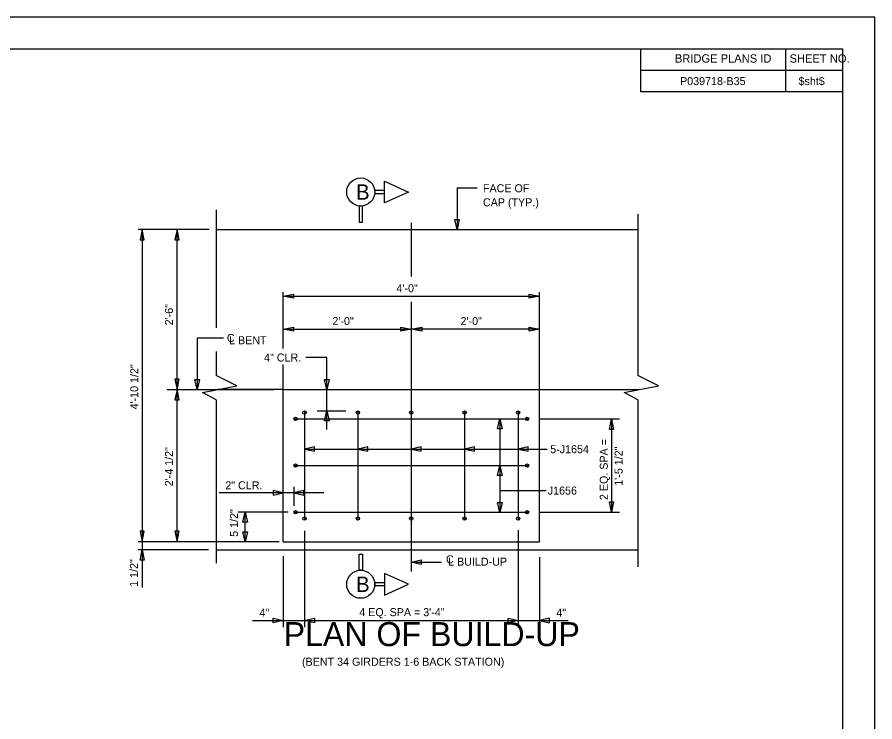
# Model space of a CAD drawing. Extents: x -133.1 to -97, y -110.1 to -88.1.
# Drawn here: x -110.53 to -97.14, y -99.1 to -88.1 of the extents above; entities that cross this region are included whole.
import ezdxf

# ---------------------------------------------------------------- set-up
doc = ezdxf.new("R2010")
doc.units = 0
for name, color, linetype in [('BR_AUTO DIMENSION', 7, 'Continuous'), ('BR_BORDER LINES', 7, 'Continuous'), ('BR_CENTER LINES', 7, 'Continuous'), ('BR_CONCRETE', 7, 'Continuous'), ('BR_REBAR', 7, 'Continuous'), ('BR_TEXT', 7, 'Continuous'), ('Default', 7, 'Continuous'), ('Level 31', 7, 'Continuous')]:
    doc.layers.add(name, color=color, linetype=linetype)

msp = doc.modelspace()

# ---------------------------------------------------------------- linework, layer by layer
at = {"layer": 'BR_AUTO DIMENSION'}
for p, q in [((-103.664, -90.766), (-103.664, -91.416)), ((-103.664, -90.766), (-103.347, -90.766)), ((-107.532, -91.416), (-108.64, -91.416)), ((-108.577, -91.416), (-108.577, -96.291)), ((-108.035, -93.916), (-108.035, -91.416)), ((-106.378, -93.276), (-106.378, -92.397)), ((-106.378, -92.459), (-102.378, -92.459)), ((-102.378, -93.916), (-102.378, -92.397)), ((-104.378, -92.853), (-104.378, -93.218)), ((-106.378, -92.972), (-104.378, -92.972)), ((-102.378, -92.972), (-104.378, -92.972)), ((-107.721, -93.116), (-107.721, -93.916)), ((-107.309, -93.116), (-107.721, -93.116)), ((-105.698, -93.416), (-106.022, -93.416)), ((-105.698, -94.537), (-105.698, -93.416)), ((-106.378, -93.916), (-106.378, -93.526)), ((-108.092, -93.916), (-107.956, -93.916)), ((-108.035, -96.291), (-108.035, -93.916)), ((-105.849, -94.249), (-105.402, -94.249)), ((-102.994, -94.374), (-102.994, -95.832)), ((-102.387, -94.374), (-101.125, -94.374)), ((-101.254, -94.374), (-101.254, -95.832)), ((-106.045, -94.844), (-102.255, -94.844)), ((-106.211, -95.433), (-106.211, -95.73)), ((-105.743, -95.53), (-107.377, -95.53)), ((-102.994, -95.49), (-102.271, -95.49)), ((-106.299, -95.832), (-107.08, -95.832)), ((-106.972, -96.291), (-106.972, -95.832)), ((-102.387, -95.832), (-101.125, -95.832)), ((-106.045, -96.122), (-106.045, -97.623)), ((-102.711, -96.113), (-102.711, -97.623)), ((-106.44, -96.291), (-108.64, -96.291)), ((-108.577, -96.291), (-108.577, -97.005)), ((-107.543, -96.416), (-108.644, -96.416)), ((-106.378, -96.517), (-106.378, -97.623)), ((-102.378, -96.53), (-102.378, -97.623)), ((-104.378, -96.61), (-103.907, -96.61)), ((-106.859, -97.519), (-101.928, -97.519))]:
    msp.add_line(p, q, dxfattribs=at)
for points in [[(-103.628, -91.26), (-103.664, -91.416), (-103.7, -91.26)], [(-108.546, -91.578), (-108.577, -91.416), (-108.608, -91.578)], [(-108.004, -91.578), (-108.035, -91.416), (-108.067, -91.578)], [(-106.215, -92.49), (-106.378, -92.459), (-106.215, -92.428)], [(-102.54, -92.428), (-102.378, -92.459), (-102.54, -92.49)], [(-106.215, -93.003), (-106.378, -92.972), (-106.215, -92.94)], [(-104.54, -92.94), (-104.378, -92.972), (-104.54, -93.003)], [(-104.215, -93.003), (-104.378, -92.972), (-104.215, -92.94)], [(-102.54, -92.94), (-102.378, -92.972), (-102.54, -93.003)], [(-108.067, -93.753), (-108.035, -93.916), (-108.004, -93.753)], [(-107.685, -93.76), (-107.721, -93.916), (-107.757, -93.76)], [(-105.662, -93.76), (-105.698, -93.916), (-105.734, -93.76)], [(-108.004, -94.078), (-108.035, -93.916), (-108.067, -94.078)], [(-105.734, -94.405), (-105.698, -94.249), (-105.662, -94.405)], [(-103.03, -94.53), (-102.994, -94.374), (-102.958, -94.53)], [(-101.285, -94.537), (-101.254, -94.374), (-101.223, -94.537)], [(-105.889, -94.808), (-106.045, -94.844), (-105.889, -94.88)], [(-105.055, -94.808), (-105.211, -94.844), (-105.055, -94.88)], [(-104.222, -94.808), (-104.378, -94.844), (-104.222, -94.88)], [(-103.389, -94.808), (-103.545, -94.844), (-103.389, -94.88)], [(-102.555, -94.808), (-102.711, -94.844), (-102.555, -94.88)], [(-103.03, -95.259), (-102.994, -95.103), (-102.958, -95.259)], [(-106.534, -95.566), (-106.378, -95.53), (-106.534, -95.494)], [(-106.055, -95.494), (-106.211, -95.53), (-106.055, -95.566)], [(-102.958, -95.677), (-102.994, -95.833), (-103.03, -95.677)], [(-101.223, -95.67), (-101.254, -95.832), (-101.285, -95.67)], [(-107.008, -95.988), (-106.972, -95.832), (-106.936, -95.988)], [(-108.608, -96.128), (-108.577, -96.291), (-108.546, -96.128)], [(-108.067, -96.128), (-108.035, -96.291), (-108.004, -96.128)], [(-106.936, -96.135), (-106.972, -96.291), (-107.008, -96.135)], [(-108.608, -96.578), (-108.577, -96.416), (-108.546, -96.578)], [(-104.222, -96.646), (-104.378, -96.61), (-104.222, -96.574)], [(-106.534, -97.483), (-106.378, -97.519), (-106.534, -97.555)], [(-105.889, -97.555), (-106.045, -97.519), (-105.889, -97.483)], [(-102.867, -97.483), (-102.711, -97.519), (-102.867, -97.555)], [(-102.222, -97.483), (-102.378, -97.519), (-102.222, -97.555)]]:
    msp.add_lwpolyline(points, close=True, dxfattribs=at)
at = {"layer": 'BR_BORDER LINES'}
for p, q in [((-97.642, -88.603), (-131.308, -88.603)), ((-100.794, -89.269), (-100.794, -88.603)), ((-98.528, -89.269), (-98.528, -88.603)), ((-97.642, -109.603), (-97.642, -88.603)), ((-100.794, -88.932), (-97.642, -88.932)), ((-98.528, -88.932), (-97.642, -88.932)), ((-97.642, -89.269), (-100.794, -89.269))]:
    msp.add_line(p, q, dxfattribs=at)
at = {"layer": 'BR_CENTER LINES'}
for p, q in [((-104.378, -91.315), (-104.378, -92.151)), ((-104.378, -92.546), (-104.378, -93.917)), ((-108.19, -93.916), (-106.523, -93.916)), ((-104.378, -93.917), (-104.378, -96.755))]:
    msp.add_line(p, q, dxfattribs=at)
at = {"layer": 'BR_CONCRETE'}
for p, q in [((-107.422, -91.416), (-100.84, -91.416)), ((-106.378, -93.916), (-107.403, -93.916)), ((-106.378, -96.291), (-106.378, -93.916)), ((-106.378, -93.916), (-102.378, -93.916)), ((-102.378, -96.291), (-102.378, -93.916)), ((-102.378, -93.916), (-100.82, -93.916)), ((-106.378, -96.291), (-102.378, -96.291)), ((-107.422, -96.416), (-100.84, -96.416))]:
    msp.add_line(p, q, dxfattribs=at)
at = {"layer": 'BR_REBAR'}
for p, q in [((-106.045, -94.249), (-106.045, -95.957)), ((-105.211, -94.249), (-105.211, -95.957)), ((-104.378, -94.249), (-104.378, -95.957)), ((-103.545, -94.249), (-103.545, -95.957)), ((-102.711, -94.249), (-102.711, -95.957)), ((-106.211, -94.374), (-102.545, -94.374)), ((-106.211, -95.103), (-102.545, -95.103)), ((-106.211, -95.832), (-102.545, -95.832))]:
    msp.add_line(p, q, dxfattribs=at)
for centre, radius in [((-106.045, -94.275), 0.0261), ((-105.211, -94.275), 0.0261), ((-104.378, -94.275), 0.0261), ((-103.545, -94.275), 0.0261), ((-102.711, -94.275), 0.0261), ((-106.185, -94.374), 0.026), ((-102.571, -94.374), 0.026), ((-106.185, -95.103), 0.026), ((-102.571, -95.103), 0.026), ((-106.185, -95.832), 0.026), ((-102.571, -95.832), 0.026), ((-106.045, -95.931), 0.0261), ((-105.211, -95.931), 0.0261), ((-104.378, -95.931), 0.0261), ((-103.545, -95.931), 0.0261), ((-102.711, -95.931), 0.0261)]:
    msp.add_circle(centre, radius, dxfattribs=at)
at = {"layer": 'BR_TEXT'}
for points in [[(-104.798, -90.663), (-104.422, -90.832), (-104.798, -91.001)], [(-104.948, -90.857), (-104.798, -90.857), (-104.798, -90.807), (-104.948, -90.807)], [(-105.192, -91.301), (-105.142, -91.301), (-105.142, -91.051), (-105.192, -91.051)], [(-105.192, -96.485), (-105.142, -96.485), (-105.142, -96.736), (-105.192, -96.736)], [(-104.798, -97.123), (-104.422, -96.955), (-104.798, -96.786)], [(-104.948, -96.929), (-104.798, -96.929), (-104.798, -96.98), (-104.948, -96.98)]]:
    msp.add_lwpolyline(points, close=True, dxfattribs=at)
for centre in [(-105.167, -90.832), (-105.167, -96.955)]:
    msp.add_circle(centre, 0.219, dxfattribs=at)
at = {"layer": 'Default'}
for p, q in [((-107.422, -91.111), (-107.422, -92.95)), ((-100.84, -91.176), (-100.84, -93.695)), ((-107.422, -93.322), (-107.422, -93.695)), ((-107.422, -94.078), (-107.422, -96.628)), ((-100.84, -94.078), (-100.84, -96.683))]:
    msp.add_line(p, q, dxfattribs=at)
for points in [[(-107.422, -94.078), (-107.639, -93.96), (-107.103, -93.859), (-107.422, -93.695)], [(-100.84, -94.078), (-101.056, -93.96), (-100.52, -93.859), (-100.84, -93.695)]]:
    msp.add_lwpolyline(points, dxfattribs=at)
at = {"layer": 'Level 31'}
msp.add_lwpolyline([(-133.141, -110.103), (-97.141, -110.103), (-97.141, -88.103), (-133.141, -88.103)], close=True, dxfattribs=at)

# ---------------------------------------------------------------- texts
at = {"layer": 'BR_AUTO DIMENSION'}
for s, p in [('FACE OF', (-103.259, -90.836)), ('CAP (TYP.)', (-103.259, -91.055)), ('4\'-0"', (-104.609, -92.397)), ('2\'-0"', (-105.609, -92.909)), ('2\'-0"', (-103.609, -92.909)), ('4" CLR.', (-106.676, -93.478)), ('5-J1654', (-102.209, -94.909)), ('2" CLR.', (-107.281, -95.473)), ('J1656', (-102.247, -95.555)), ('C', (-103.836, -96.628)), ('L BUILD-UP', (-103.802, -96.665)), ('4 EQ. SPA = 3\'-4"', (-105.19, -97.453)), ('(BENT 34 GIRDERS 1-6 BACK STATION)', (-106.084, -98.227))]:
    msp.add_text(s, height=0.125, dxfattribs=at).set_placement(p)
for s, rotation, p in [('2\'-6"', 90, (-108.098, -92.914)), ('4\'-10 1/2"', 90, (-108.64, -94.226)), ('2 EQ. SPA =', 90, (-101.31, -95.641)), ('2\'-4 1/2"', 90, (-108.098, -95.426)), ('1\'-5 1/2"', 90, (-101.079, -95.417)), ('4"', 360, (-106.748, -97.461)), ('4"', 360, (-102.114, -97.461))]:
    msp.add_text(s, height=0.125, rotation=rotation, dxfattribs=at).set_placement(p)
at = {"layer": 'BR_TEXT'}
for s, height, p in [('BRIDGE PLANS ID', 0.13, (-100.263, -88.812)), ('SHEET NO.', 0.13, (-98.472, -88.812)), ('P039718-B35', 0.125, (-100.182, -89.163)), ('$sht$', 0.125, (-98.332, -89.163)), ('B', 0.24, (-105.242, -90.952)), ('B', 0.24, (-105.242, -97.075)), ('PLAN OF BUILD-UP', 0.375, (-106.371, -97.921))]:
    msp.add_text(s, height=height, dxfattribs=at).set_placement(p)
for s, rotation, p in [('C', 360, (-107.257, -93.173)), ('L BENT', 360, (-107.222, -93.209)), ('5 1/2"', 90, (-107.083, -96.215)), ('1 1/2"', 90, (-108.646, -96.995))]:
    msp.add_text(s, height=0.125, rotation=rotation, dxfattribs=at).set_placement(p)

doc.saveas('drawing.dxf')
